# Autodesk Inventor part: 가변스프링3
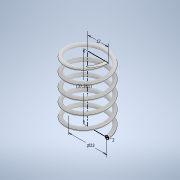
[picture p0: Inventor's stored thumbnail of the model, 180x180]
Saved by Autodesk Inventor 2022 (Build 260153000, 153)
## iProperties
Created: 2021-07
Part Number: 가변스프링3
Material: 일반
Document SubType Name: Modeling
Designer: micke
Density: 1 g/cm^3
Appearance: 기본값
Author: micke
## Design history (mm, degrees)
sketch "스케치1"
  geometry: L1 (0, 0)-(0, 37.261); L2 (0, 37.261)-(12, 37.261); L3 (0, 0)-(11, 0); C1 r 1 at (11, 0)
  constraints: 6 end point, 2 horizontal, 1 centre point, 1 coincident, 1 vertical
  dimensions: "d0" = 37.2612 distance of L1.start L1.end (derived); "d1" = 2 diameter of C1; "d2" = 22 diameter of L3.end L1; "d3" = 12 distance of L1.end L2.end
feature "코일1" sketch "스케치1" pitch "d4" = 10; turns "d6" = 5; dims "d5" = 37.2612 (= d0), "d7" = 0, angle "d8" = 90 deg, angle "d9" = 90 deg, "d10" = 0, "d11" = 0
sketch "스케치2"
  geometry: L1 (37.261, 12.5)-(0, 12.5); L2 (0, 12.5)-(0, -12.5); L3 (0, -12.5)-(37.261, -12.5); L4 (37.261, -12.5)-(37.261, 12.5); 2 further points
  constraints: 8 end point, 2 parallel, 1 coincident, 1 horizontal, 1 midpoint, 1 perpendicular
  dimensions: "d12" = 37.2612 distance of L1.start L1.end (= d0); "d13" = 25 distance of L3.end L1.start
extrude "돌출1" sketch "스케치2" extent not by distance; stored distance "d14" = 0; taper "d15" = 0 deg
node "솔리드1"
feature "A9D066F2-1C7D-4E18-AEED-F7BC21143FA4" dims "d4" = 10, "d5" = 37.2612 (= d0), "d6" = 50, "d7" = 0, "d8" = 90 deg, "d9" = 90 deg, "d10" = 0, "d11" = 0
